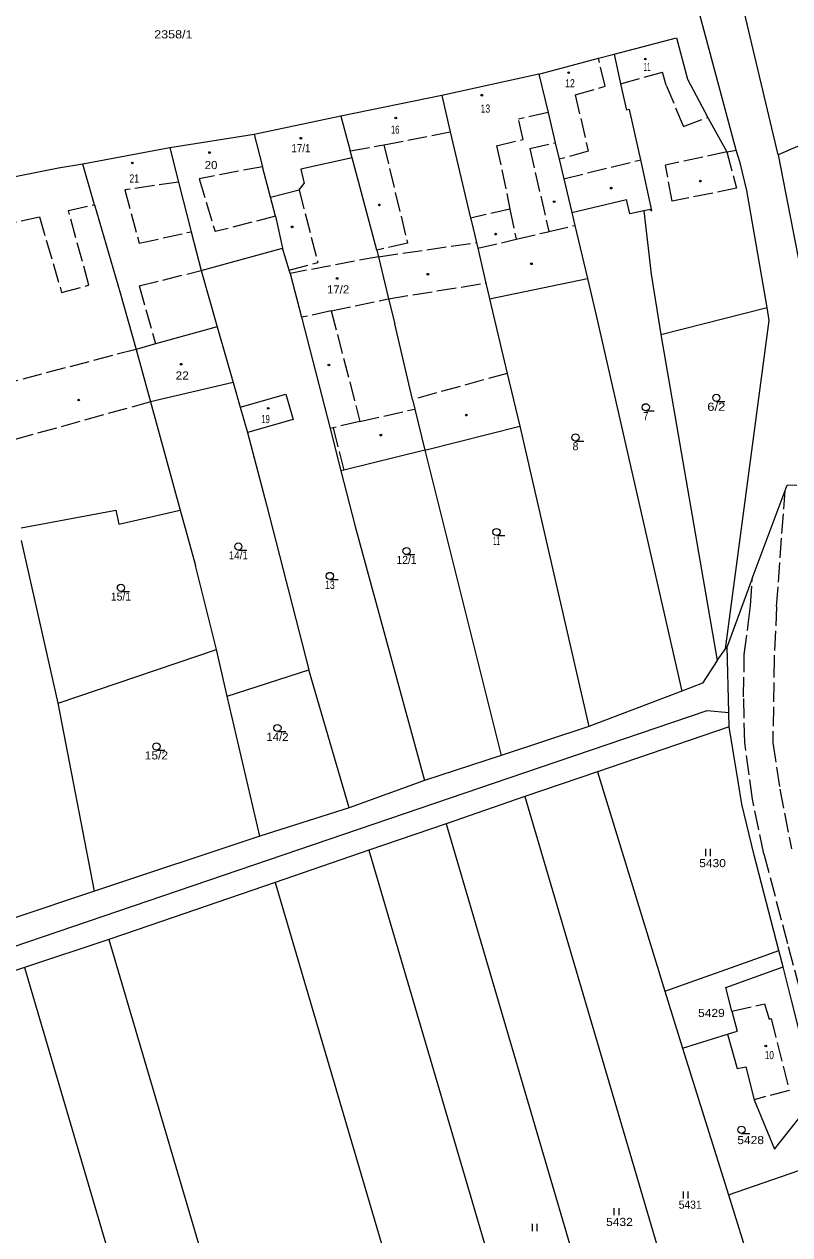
# Model space of a CAD drawing. Extents: x -590528 to -586543, y -1119609 to -1116685.
# Drawn here: x -588830.7 to -588671, y -1118783.3 to -1118530.4 of the extents above; entities that cross this region are included whole.
import ezdxf
from ezdxf.enums import TextEntityAlignment as Align

# ---------------------------------------------------------------- set-up
doc = ezdxf.new("R2010")
doc.units = 0
doc.header["$LTSCALE"] = 0.68
doc.linetypes.add('LONG_DASHED', pattern=[7.5, 6, -1.5])
for name, color, linetype, lineweight in [('1', 7, 'Continuous', 13), ('2', 7, 'LONG_DASHED', 13), ('3', 7, 'Continuous', 13), ('6', 7, 'Continuous', 13)]:
    doc.layers.add(name, color=color, linetype=linetype, lineweight=lineweight)

msp = doc.modelspace()

# ---------------------------------------------------------------- linework, layer by layer
at = {"layer": '1'}
for p, q in [((-588723.32, -1118540.86), (-588743.59, -1118545.31)), ((-588743.59, -1118545.31), (-588764.62, -1118549.68)), ((-588743.59, -1118545.31), (-588741.8, -1118552.94)), ((-588764.62, -1118549.68), (-588762.69, -1118556.9)), ((-588704.38, -1118548.26), (-588705.06, -1118548.41)), ((-588702.07, -1118558.77), (-588704.38, -1118548.26)), ((-588687.92, -1118550.22), (-588684.12, -1118557.13)), ((-588741.8, -1118552.94), (-588737.56, -1118570.96)), ((-588762.31, -1118558.33), (-588762.69, -1118556.9)), ((-588684.12, -1118557.13), (-588682.13, -1118556.73)), ((-588681.3, -1118559.37), (-588682.13, -1118556.73)), ((-588818.49, -1118559.67), (-588823.59, -1118560.51)), ((-588816.09, -1118568.14), (-588818.49, -1118559.67)), ((-588757.13, -1118577.64), (-588762.31, -1118558.33)), ((-588719.09, -1118558.66), (-588718.12, -1118562.72)), ((-588699.76, -1118569.33), (-588702.07, -1118558.77)), ((-588679.92, -1118565.18), (-588681.3, -1118559.37)), ((-588673.36, -1118557.76), (-588668.24, -1118584.17)), ((-588773.37, -1118565.05), (-588772.28, -1118563.73)), ((-588718.12, -1118562.72), (-588716.45, -1118569.74)), ((-588779.32, -1118566.58), (-588773.37, -1118565.05)), ((-588716.45, -1118569.74), (-588705.06, -1118567.06)), ((-588704.36, -1118570.03), (-588705.06, -1118567.06)), ((-588816.09, -1118568.14), (-588810.67, -1118586.56)), ((-588716.45, -1118569.74), (-588715.8, -1118572.46)), ((-588701.42, -1118569.45), (-588704.36, -1118570.03)), ((-588700.02, -1118569.17), (-588701.42, -1118569.45)), ((-588701.42, -1118569.45), (-588699.9, -1118582.65)), ((-588778.29, -1118570.57), (-588776.8, -1118577.2)), ((-588737.56, -1118570.96), (-588737.53, -1118571.07)), ((-588793.8, -1118581.86), (-588776.8, -1118577.2)), ((-588775.86, -1118580.41), (-588776.8, -1118577.2)), ((-588757.13, -1118577.64), (-588756.77, -1118579)), ((-588756.77, -1118579), (-588754.67, -1118587.77)), ((-588775.24, -1118582.5), (-588772.88, -1118591.66)), ((-588699.9, -1118582.65), (-588697.88, -1118595.22)), ((-588733.62, -1118587.8), (-588713.16, -1118583.58)), ((-588810.67, -1118586.56), (-588807.37, -1118598.35)), ((-588754.67, -1118587.77), (-588753.41, -1118593.05)), ((-588733.62, -1118587.8), (-588729.93, -1118603.37)), ((-588697.88, -1118595.22), (-588675.7, -1118589.58)), ((-588772.88, -1118591.66), (-588766.9, -1118614.89)), ((-588711.27, -1118591.54), (-588693.51, -1118669.76)), ((-588684.4, -1118660.87), (-588675.23, -1118592.33)), ((-588749.66, -1118608.8), (-588753.41, -1118593.05)), ((-588697.88, -1118595.22), (-588686.1, -1118663.34)), ((-588807.37, -1118598.35), (-588804.37, -1118609.31)), ((-588787.13, -1118605.25), (-588804.37, -1118609.31)), ((-588787.13, -1118605.25), (-588785.66, -1118610.4)), ((-588729.93, -1118603.37), (-588727.31, -1118614.36)), ((-588785.66, -1118610.4), (-588776.12, -1118607.68)), ((-588776.12, -1118607.68), (-588774.6, -1118613.02)), ((-588785.66, -1118610.4), (-588784.14, -1118615.74)), ((-588774.6, -1118613.02), (-588784.14, -1118615.74)), ((-588766.9, -1118614.89), (-588764.62, -1118623.74)), ((-588747.13, -1118619.44), (-588727.31, -1118614.36)), ((-588727.31, -1118614.36), (-588712.92, -1118677.09)), ((-588784.14, -1118615.74), (-588780.13, -1118630.83)), ((-588747.13, -1118619.44), (-588731.18, -1118683.19)), ((-588764.62, -1118623.74), (-588761.63, -1118635.38)), ((-588678.78, -1118646.19), (-588671.93, -1118627.82)), ((-588671.93, -1118627.82), (-588671.52, -1118626.71)), ((-588669.51, -1118626.8), (-588671.52, -1118626.71)), ((-588831.35, -1118635.65), (-588811.61, -1118631.91)), ((-588811.61, -1118631.91), (-588811, -1118634.84)), ((-588811, -1118634.84), (-588798.16, -1118631.97)), ((-588780.13, -1118630.83), (-588771.3, -1118665.26)), ((-588761.63, -1118635.38), (-588747.17, -1118688.41)), ((-588823.66, -1118672.27), (-588831.29, -1118638.24)), ((-588790.57, -1118661.04), (-588795, -1118643.49)), ((-588678.78, -1118646.19), (-588684.06, -1118660.38)), ((-588788.4, -1118670.8), (-588790.57, -1118661.04)), ((-588762.94, -1118694.07), (-588771.3, -1118665.26)), ((-588726.26, -1118686.74), (-588688.17, -1118673.76)), ((-588683.59, -1118677.21), (-588683.67, -1118674.22)), ((-588895.2, -1118744.31), (-588726.26, -1118686.74)), ((-588680.98, -1118693.31), (-588681.75, -1118688.57)), ((-588726.22, -1118691.75), (-588678.42, -1118854.34)), ((-588762.94, -1118694.07), (-588781.53, -1118700)), ((-588742.7, -1118697.42), (-588758.81, -1118702.96)), ((-588742.7, -1118697.42), (-588695.39, -1118858.32)), ((-588758.81, -1118702.96), (-588711.98, -1118862.22)), ((-588813.05, -1118721.57), (-588767.86, -1118875.33)), ((-588697.04, -1118732.42), (-588693.35, -1118744.26)), ((-588683.02, -1118736.58), (-588681.96, -1118740.73))]:
    msp.add_line(p, q, dxfattribs=at)
for points in [[(-588682.13, -1118556.73), (-588691.38, -1118522.13), (-588690.83, -1118516.18), (-588689.62, -1118511.77)], [(-588673.36, -1118557.76), (-588681.44, -1118523.65), (-588680.66, -1118514.72)], [(-588707.63, -1118536.69), (-588694.63, -1118533.31), (-588692.32, -1118541.96)], [(-588723.32, -1118540.86), (-588710.89, -1118537.56), (-588707.63, -1118536.69)], [(-588707.63, -1118536.69), (-588706.27, -1118542.88), (-588705.06, -1118548.41)], [(-588723.32, -1118540.86), (-588721.41, -1118548.88), (-588719.91, -1118555.19), (-588719.09, -1118558.66)], [(-588692.32, -1118541.96), (-588688.09, -1118549.9), (-588687.92, -1118550.22)], [(-588764.62, -1118549.68), (-588782.74, -1118553.46), (-588780.98, -1118560.21)], [(-588782.74, -1118553.46), (-588800.36, -1118556.29), (-588818.49, -1118559.67)], [(-588800.36, -1118556.29), (-588798.52, -1118563.45), (-588795.87, -1118573.78), (-588793.8, -1118581.86), (-588790.45, -1118593.62), (-588787.13, -1118605.25)], [(-588661.07, -1118560.26), (-588669.33, -1118556), (-588673.36, -1118557.76)], [(-588762.31, -1118558.33), (-588772.98, -1118560.71), (-588772.28, -1118563.73)], [(-588823.59, -1118560.51), (-588850.12, -1118565.82), (-588847.53, -1118575.03)], [(-588778.29, -1118570.57), (-588779.32, -1118566.58), (-588780.98, -1118560.21)], [(-588675.23, -1118592.33), (-588675.7, -1118589.58), (-588679.92, -1118565.18)], [(-588700.02, -1118569.17), (-588699.98, -1118569.37), (-588699.76, -1118569.33)], [(-588737.53, -1118571.07), (-588736.35, -1118576.05), (-588736.07, -1118577.25), (-588734.37, -1118584.51)], [(-588715.8, -1118572.46), (-588713.16, -1118583.58), (-588711.27, -1118591.54)], [(-588775.24, -1118582.5), (-588775.45, -1118581.81), (-588775.86, -1118580.41)], [(-588734.37, -1118584.51), (-588733.7, -1118587.44), (-588733.62, -1118587.8)], [(-588790.45, -1118593.62), (-588803.33, -1118597.22), (-588807.37, -1118598.35)], [(-588804.37, -1118609.31), (-588798.16, -1118631.97), (-588795, -1118643.49)], [(-588749.66, -1118608.8), (-588749.18, -1118610.81), (-588747.13, -1118619.44)], [(-588747.13, -1118619.44), (-588764.02, -1118623.59), (-588764.62, -1118623.74)], [(-588816.06, -1118711.54), (-588823.66, -1118672.27), (-588790.57, -1118661.04)], [(-588688.17, -1118673.76), (-588683.67, -1118674.22), (-588684.06, -1118660.38)], [(-588686.1, -1118663.34), (-588684.4, -1118660.87), (-588684.06, -1118660.38)], [(-588686.1, -1118663.34), (-588689.16, -1118668.06), (-588693.51, -1118669.76), (-588712.92, -1118677.09)], [(-588781.53, -1118700), (-588788.4, -1118670.8), (-588771.3, -1118665.26)], [(-588712.92, -1118677.09), (-588731.18, -1118683.19), (-588747.17, -1118688.41), (-588762.94, -1118694.07)], [(-588681.75, -1118688.57), (-588683.59, -1118677.21), (-588711.11, -1118686.55)], [(-588711.11, -1118686.55), (-588726.22, -1118691.75), (-588742.7, -1118697.42)], [(-588711.11, -1118686.55), (-588697.04, -1118732.42), (-588682.15, -1118727.09), (-588677.26, -1118725.34), (-588673.21, -1118723.89), (-588678.38, -1118704.02), (-588680.98, -1118693.31)], [(-588781.53, -1118700), (-588816.06, -1118711.54), (-588833.09, -1118717.21), (-588849.18, -1118722.57)], [(-588758.81, -1118702.96), (-588778.33, -1118709.68), (-588807.15, -1118719.6), (-588813.05, -1118721.57), (-588830.64, -1118727.44), (-588847.23, -1118732.97), (-588863.75, -1118738.48)], [(-588778.33, -1118709.68), (-588732.07, -1118866.93), (-588711.98, -1118862.22)], [(-588683.02, -1118736.58), (-588684.3, -1118731.59), (-588672.35, -1118727.29), (-588673.21, -1118723.89)], [(-588830.64, -1118727.44), (-588785.91, -1118879.56), (-588767.86, -1118875.33)], [(-588683.93, -1118741.34), (-588681.92, -1118748.54), (-588680.14, -1118748.16), (-588678.4, -1118755.05), (-588674.17, -1118765.39), (-588665.28, -1118754.22), (-588667.31, -1118747.26), (-588670.58, -1118734.28), (-588672.35, -1118727.29)], [(-588693.35, -1118744.26), (-588683.93, -1118741.34), (-588681.96, -1118740.73)], [(-588693.35, -1118744.26), (-588683.78, -1118774.9), (-588661.64, -1118767.3), (-588662.44, -1118763.97), (-588665.28, -1118754.22)], [(-588683.78, -1118774.9), (-588660.47, -1118850.13), (-588636.3, -1118844.46)]]:
    msp.add_lwpolyline(points, dxfattribs=at)
at = {"layer": '2'}
for p, q in [((-588706.27, -1118542.88), (-588697.55, -1118540.48)), ((-588696.75, -1118543.21), (-588697.55, -1118540.48)), ((-588696.75, -1118543.21), (-588693.15, -1118551.78)), ((-588715.73, -1118545.18), (-588713.01, -1118556.99)), ((-588721.41, -1118548.88), (-588727.59, -1118550.26)), ((-588726.61, -1118554.5), (-588727.59, -1118550.26)), ((-588693.15, -1118551.78), (-588688.09, -1118549.9)), ((-588755.68, -1118555.65), (-588741.8, -1118552.94)), ((-588732.13, -1118555.85), (-588726.61, -1118554.5)), ((-588762.69, -1118556.9), (-588755.68, -1118555.65)), ((-588755.68, -1118555.65), (-588750.72, -1118576.19)), ((-588732.13, -1118555.85), (-588729.36, -1118569.07)), ((-588725.2, -1118556.44), (-588719.91, -1118555.19)), ((-588725.2, -1118556.44), (-588721.25, -1118573.74)), ((-588713.01, -1118556.99), (-588719.09, -1118558.66)), ((-588684.12, -1118557.13), (-588696.92, -1118559.86)), ((-588718.12, -1118562.72), (-588702.07, -1118558.77)), ((-588695.48, -1118567.41), (-588696.92, -1118559.86)), ((-588780.98, -1118560.21), (-588794.25, -1118562.71)), ((-588798.52, -1118563.45), (-588809.74, -1118565.03)), ((-588794.25, -1118562.71), (-588790.89, -1118573.77)), ((-588809.74, -1118565.03), (-588806.74, -1118576.2)), ((-588773.37, -1118565.05), (-588769.45, -1118580.21)), ((-588821.52, -1118569.33), (-588816.09, -1118568.14)), ((-588817.22, -1118584.93), (-588821.52, -1118569.33)), ((-588729.36, -1118569.07), (-588737.56, -1118570.96)), ((-588729.36, -1118569.07), (-588728.05, -1118575.35)), ((-588778.29, -1118570.57), (-588790.89, -1118573.77)), ((-588806.74, -1118576.2), (-588795.87, -1118573.78)), ((-588750.72, -1118576.19), (-588757.13, -1118577.64)), ((-588756.77, -1118579), (-588736.35, -1118576.05)), ((-588756.77, -1118579), (-588775.24, -1118582.5)), ((-588806.71, -1118585.12), (-588793.8, -1118581.86)), ((-588775.45, -1118581.81), (-588769.45, -1118580.21)), ((-588822.92, -1118586.48), (-588817.22, -1118584.93)), ((-588806.71, -1118585.12), (-588803.33, -1118597.22)), ((-588766.64, -1118590.33), (-588772.88, -1118591.66)), ((-588766.64, -1118590.33), (-588760.67, -1118613.4)), ((-588807.37, -1118598.35), (-588838.1, -1118606.42)), ((-588729.93, -1118603.37), (-588749.66, -1118608.8)), ((-588804.37, -1118609.31), (-588835.6, -1118618.01)), ((-588760.67, -1118613.4), (-588749.18, -1118610.81)), ((-588766.28, -1118614.74), (-588766.9, -1118614.89)), ((-588673.71, -1118652.04), (-588671.93, -1118627.82)), ((-588673.01, -1118690.19), (-588670.62, -1118702.66)), ((-588676.35, -1118703.69), (-588678.73, -1118692.26))]:
    msp.add_line(p, q, dxfattribs=at)
for points in [[(-588715.73, -1118545.18), (-588709.48, -1118543.42), (-588710.89, -1118537.56)], [(-588684.12, -1118557.13), (-588682.05, -1118564.7), (-588695.48, -1118567.41)], [(-588841.33, -1118573.67), (-588827.56, -1118570.65), (-588822.92, -1118586.48)], [(-588721.41, -1118573.78), (-588721.25, -1118573.74), (-588715.8, -1118572.46)], [(-588736.07, -1118577.25), (-588728.05, -1118575.35), (-588721.41, -1118573.78)], [(-588766.64, -1118590.33), (-588754.67, -1118587.77), (-588734.37, -1118584.51)], [(-588760.67, -1118613.4), (-588766.28, -1118614.74), (-588764.02, -1118623.59)], [(-588678.73, -1118692.26), (-588680.36, -1118680.45), (-588680.59, -1118670.89), (-588680.45, -1118662.11), (-588679.62, -1118655.78), (-588679.19, -1118651.91), (-588678.78, -1118646.19)], [(-588673.71, -1118652.04), (-588674.22, -1118662.8), (-588674.5, -1118680.54), (-588673.01, -1118690.19)], [(-588676.35, -1118703.69), (-588671.31, -1118723.03), (-588665.33, -1118745.2), (-588657.84, -1118771.93), (-588654.74, -1118783.01)], [(-588683.02, -1118736.58), (-588676.2, -1118735), (-588675.23, -1118738.27), (-588674.86, -1118738.13), (-588671.09, -1118753.12), (-588678.4, -1118755.05)]]:
    msp.add_lwpolyline(points, dxfattribs=at)
at = {"layer": '6'}
for p, q in [((-588686.29, -1118609.24), (-588684.54, -1118609.24)), ((-588701.01, -1118611.2), (-588699.26, -1118611.2)), ((-588715.68, -1118617.5), (-588713.93, -1118617.5)), ((-588732.17, -1118637.25), (-588730.42, -1118637.25)), ((-588786.04, -1118640.26), (-588784.29, -1118640.26)), ((-588750.93, -1118641.23), (-588749.18, -1118641.23)), ((-588766.94, -1118646.43), (-588765.19, -1118646.43)), ((-588810.54, -1118648.89), (-588808.79, -1118648.89)), ((-588777.88, -1118678.18), (-588776.13, -1118678.18)), ((-588803.14, -1118682.04), (-588801.39, -1118682.04)), ((-588688.51, -1118704.18), (-588688.51, -1118702.68)), ((-588687.51, -1118704.18), (-588687.51, -1118702.68)), ((-588681.04, -1118762.08), (-588679.29, -1118762.08)), ((-588693.15, -1118775.7), (-588693.15, -1118774.2)), ((-588692.15, -1118775.7), (-588692.15, -1118774.2)), ((-588707.59, -1118779.18), (-588707.59, -1118777.68)), ((-588706.59, -1118779.18), (-588706.59, -1118777.68)), ((-588724.68, -1118782.5), (-588724.68, -1118781)), ((-588723.68, -1118782.5), (-588723.68, -1118781))]:
    msp.add_line(p, q, dxfattribs=at)
for centre, radius in [((-588701.0902, -1118537.7204), 0.175), ((-588717.1002, -1118540.5804), 0.175), ((-588735.2302, -1118545.2704), 0.175), ((-588753.1802, -1118550.0404), 0.175), ((-588772.9802, -1118554.2504), 0.175), ((-588792.0502, -1118557.2604), 0.175), ((-588808.1702, -1118559.4204), 0.175), ((-588708.2202, -1118564.6804), 0.175), ((-588689.6302, -1118563.2104), 0.175), ((-588720.1302, -1118567.5004), 0.175), ((-588756.6102, -1118568.1904), 0.175), ((-588774.8202, -1118572.7804), 0.175), ((-588732.3402, -1118574.2904), 0.175), ((-588746.4902, -1118582.6604), 0.175), ((-588724.8702, -1118580.4804), 0.175), ((-588765.4202, -1118583.5404), 0.175), ((-588797.9702, -1118601.4504), 0.175), ((-588767.1502, -1118601.6104), 0.175), ((-588686.29, -1118608.49), 0.75), ((-588819.3602, -1118608.9404), 0.175), ((-588779.8002, -1118610.6604), 0.175), ((-588701.01, -1118610.45), 0.75), ((-588738.4602, -1118612.0804), 0.175), ((-588756.3102, -1118616.2604), 0.175), ((-588715.68, -1118616.75), 0.75), ((-588732.17, -1118636.5), 0.75), ((-588786.04, -1118639.51), 0.75), ((-588750.93, -1118640.48), 0.75), ((-588766.94, -1118645.68), 0.75), ((-588810.54, -1118648.14), 0.75), ((-588777.88, -1118677.43), 0.75), ((-588803.14, -1118681.29), 0.75), ((-588675.9602, -1118743.8304), 0.175), ((-588681.04, -1118761.33), 0.75)]:
    msp.add_circle(centre, radius, dxfattribs=at)

# ---------------------------------------------------------------- texts
at = {"layer": '3'}
for s, width, p in [('2358/1', 1.15, (-588799.6005, -1118533.41)), ('11', 0.45, (-588700.7405, -1118540.22)), ('12', 0.8, (-588716.83, -1118543.64)), ('13', 0.8, (-588734.4905, -1118548.92)), ('16', 0.7, (-588753.3105, -1118553.31)), ('17/1', 0.9, (-588772.9805, -1118557.19)), ('20', 1.05, (-588791.74, -1118560.71)), ('21', 0.8, (-588807.76, -1118563.51)), ('17/2', 1.05, (-588765.22, -1118586.68)), ('22', 1.1, (-588797.75, -1118604.66)), ('6/2', 1.2, (-588686.29, -1118611.19)), ('19', 0.7, (-588780.3605, -1118613.76)), ('7', 0.85, (-588701.01, -1118613.15)), ('8', 0.95, (-588715.6805, -1118619.45)), ('11', 0.45, (-588732.1705, -1118639.2)), ('14/1', 0.9, (-588786.0405, -1118642.21)), ('12/1', 0.95, (-588750.93, -1118643.18)), ('13', 0.8, (-588766.9405, -1118648.38)), ('15/1', 0.95, (-588810.5405, -1118650.84)), ('14/2', 1.05, (-588777.88, -1118680.13)), ('15/2', 1.1, (-588803.14, -1118683.99))]:
    msp.add_text(s, height=1.7, dxfattribs=dict(at, width=width)).set_placement(p, align=Align.CENTER)
for s, width, p in [('5430', 1.1, (-588689.853, -1118706.5)), ('5429', 1.1, (-588690.093, -1118737.79)), ('10', 0.75, (-588676.167, -1118746.59)), ('5428', 1.1, (-588681.903, -1118764.33)), ('5431', 0.95, (-588694.143, -1118777.83)), ('5432', 1.1, (-588709.283, -1118781.43))]:
    msp.add_text(s, height=1.7, dxfattribs=dict(at, width=width)).set_placement(p)

doc.saveas('drawing.dxf')
